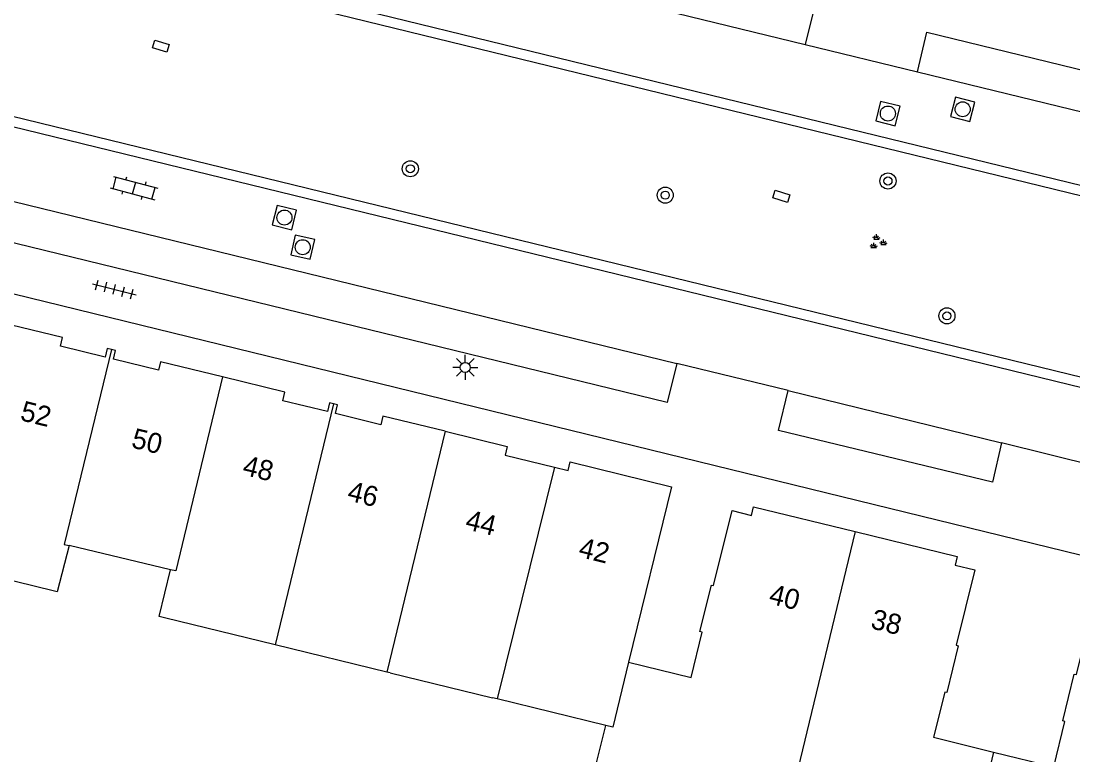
# Model space of a CAD drawing. Extents: x 125000 to 129004, y 397500 to 399008.
# Drawn here: x 126516.3 to 126568.7, y 397968.6 to 398005.2 of the extents above; entities that cross this region are included whole.
import ezdxf

# ---------------------------------------------------------------- set-up
doc = ezdxf.new("R2010")
doc.units = 0
for name, color, linetype in [('gg-anno-huisnummerreeks BGT', 7, 'Continuous'), ('gg-bbg-hoofdgebouw', 7, 'Continuous'), ('gg-bbg-tussenscheiding', 7, 'Continuous'), ('gg-knt-verharding', 7, 'Continuous'), ('gg-knt-verharding nz', 7, 'Continuous'), ('gt-symb-boom', 7, 'Continuous'), ('gt-symb-groenvak', 7, 'Continuous'), ('gt-symb-klinker verharding', 7, 'Continuous'), ('gt-symb-kolk center center', 7, 'Continuous'), ('gt-symb-lichtmast', 7, 'Continuous'), ('gt-symb-rioolschacht', 7, 'Continuous'), ('gt-symb-tegel verharding', 7, 'Continuous')]:
    doc.layers.add(name, color=color, linetype=linetype)

# ---------------------------------------------------------------- blocks, each defined once
blk = doc.blocks.new('gt0-BOOM')
at = {"layer": 'gt-symb-boom'}
for radius in [0.4, 0.2]:
    blk.add_circle((0, 0), radius, dxfattribs=at)
blk = doc.blocks.new('gt0-KOLKCC')
at = {"layer": 'gt-symb-kolk center center'}
blk.add_lwpolyline([(-0.375, 0.2), (0.375, 0.2), (0.375, -0.2), (-0.375, -0.2)], close=True, dxfattribs=at)
blk = doc.blocks.new('gt0-GRVAK')
at = {"layer": 'gt-symb-groenvak'}
for p, q in [((-0.11, 0.189), (-0.228, 0.24)), ((-0.182, 0.153), (0.088, 0.153)), ((-0.091, 0.211), (-0.156, 0.322)), ((-0.047, 0.214), (-0.047, 0.393)), ((-0.004, 0.211), (0.061, 0.322)), ((0.015, 0.189), (0.133, 0.24)), ((0.262, -0.052), (0.197, 0.059)), ((0.305, -0.049), (0.305, 0.13)), ((0.349, -0.052), (0.414, 0.059)), ((-0.245, -0.228), (-0.363, -0.177)), ((-0.318, -0.264), (-0.047, -0.264)), ((-0.226, -0.206), (-0.291, -0.095)), ((-0.183, -0.203), (-0.183, -0.024)), ((-0.139, -0.206), (-0.074, -0.095)), ((-0.12, -0.228), (-0.002, -0.177)), ((0.243, -0.074), (0.125, -0.023)), ((0.17, -0.11), (0.441, -0.11)), ((0.368, -0.074), (0.486, -0.023))]:
    blk.add_line(p, q, dxfattribs=at)
blk = doc.blocks.new('gt0-RS')
at = {"layer": 'gt-symb-rioolschacht'}
blk.add_lwpolyline([(-0.5, -0.5), (0.5, -0.5), (0.5, 0.5), (-0.5, 0.5)], close=True, dxfattribs=at)
blk.add_circle((0, 0), 0.375, dxfattribs=at)
blk = doc.blocks.new('gt0-LMAST')
at = {"layer": 'gt-symb-lichtmast'}
for p, q in [((-0.005, 0.246), (-0.005, 0.621)), ((-0.182, 0.173), (-0.447, 0.438)), ((0.172, 0.173), (0.437, 0.438)), ((-0.255, -0.004), (-0.63, -0.004)), ((-0.182, -0.181), (-0.447, -0.446)), ((-0.005, -0.254), (-0.005, -0.629)), ((0.437, -0.446), (0.172, -0.181)), ((0.245, -0.004), (0.62, -0.004))]:
    blk.add_line(p, q, dxfattribs=at)
blk.add_circle((-0.005, -0.004), 0.25, dxfattribs=at)
blk = doc.blocks.new('gt0-TEG1')
at = {"layer": 'gt-symb-tegel verharding'}
for p, q in [((-1.125, 0), (1.125, 0)), ((-0.9, -0.25), (-0.9, 0.25)), ((-0.45, -0.25), (-0.45, 0.25)), ((0, -0.25), (0, 0.25)), ((0.45, -0.25), (0.45, 0.25)), ((0.9, -0.25), (0.9, 0.25))]:
    blk.add_line(p, q, dxfattribs=at)
blk = doc.blocks.new('gt0-KL1')
at = {"layer": 'gt-symb-klinker verharding'}
for p, q in [((-1.15, 0.3), (1.15, 0.3)), ((-1, -0.3), (-1, 0.3)), ((-0.5, 0.3), (-0.5, 0.45)), ((0, -0.3), (0, 0.3)), ((0.5, 0.3), (0.5, 0.45)), ((1, -0.3), (1, 0.3)), ((-1.15, -0.3), (1.15, -0.3)), ((-0.5, -0.45), (-0.5, -0.3)), ((0.5, -0.45), (0.5, -0.3))]:
    blk.add_line(p, q, dxfattribs=at)

msp = doc.modelspace()

# ---------------------------------------------------------------- linework, layer by layer
at = {"layer": 'gg-bbg-hoofdgebouw'}
for p, q in [((126523.748, 397977.83), (126518.69, 397979.033)), ((126517.898, 397976.782), (126512.367, 397978.142)), ((126528.968, 397974.085), (126523.444, 397975.434)), ((126534.524, 397972.728), (126528.968, 397974.085)), ((126534.689, 397972.688), (126534.524, 397972.728)), ((126534.689, 397972.688), (126539.79, 397971.449)), ((126540.026, 397971.391), (126539.79, 397971.449)), ((126545.43, 397970.064), (126540.026, 397971.391)), ((126544.688, 397967.042), (126545.43, 397970.064))]:
    msp.add_line(p, q, dxfattribs=at)
for points in [[(126520.802, 397988.798), (126520.593, 397988.849), (126520.488, 397988.421), (126518.259, 397988.968), (126518.364, 397989.396), (126515.27, 397990.154)], [(126526.345, 397987.439), (126523.25, 397988.196), (126523.145, 397987.768), (126520.908, 397988.321), (126521.01, 397988.748), (126520.802, 397988.798)], [(126531.87, 397986.092), (126531.668, 397986.14), (126531.565, 397985.714), (126529.337, 397986.255), (126529.44, 397986.681), (126526.345, 397987.439)], [(126537.424, 397984.729), (126534.328, 397985.486), (126534.223, 397985.059), (126531.97, 397985.616), (126532.071, 397986.044), (126531.87, 397986.092)], [(126537.424, 397984.729), (126540.519, 397983.973), (126540.415, 397983.544), (126542.882, 397982.946)], [(126542.882, 397982.946), (126543.562, 397982.781), (126543.666, 397983.208), (126548.717, 397981.969), (126546.573, 397973.228)], [(126546.573, 397973.228), (126549.681, 397972.466), (126550.233, 397974.719), (126550.127, 397974.745), (126550.696, 397977.066), (126550.803, 397977.04), (126551.726, 397980.776), (126552.698, 397980.538), (126552.802, 397980.966), (126557.86, 397979.728)], [(126557.86, 397979.728), (126562.949, 397978.486), (126562.845, 397978.059), (126563.816, 397977.822), (126562.893, 397974.066), (126563, 397974.039), (126562.427, 397971.708), (126562.32, 397971.734), (126561.766, 397969.48), (126564.761, 397968.744)], [(126518.69, 397979.033), (126518.098, 397976.733), (126517.898, 397976.782)], [(126523.444, 397975.434), (126523.179, 397975.499), (126523.748, 397977.83)], [(126564.761, 397968.744), (126567.756, 397968.008), (126568.313, 397970.271), (126568.205, 397970.298), (126568.778, 397972.63), (126568.886, 397972.603), (126569.912, 397976.779), (126575.108, 397975.515), (126575.004, 397975.088), (126576.346, 397974.759), (126575.631, 397971.842), (126576.642, 397971.594), (126575.654, 397967.559), (126574.642, 397967.807), (126573.929, 397964.895)]]:
    msp.add_lwpolyline(points, dxfattribs=at)
at = {"layer": 'gg-bbg-tussenscheiding'}
for p, q in [((126531.87, 397986.092), (126528.968, 397974.085)), ((126537.424, 397984.729), (126534.524, 397972.728)), ((126542.882, 397982.946), (126540.026, 397971.391)), ((126557.86, 397979.728), (126554.796, 397967.048)), ((126564.761, 397968.744), (126563.253, 397962.507))]:
    msp.add_line(p, q, dxfattribs=at)
for points in [[(126520.802, 397988.798), (126518.455, 397979.089), (126518.69, 397979.033)], [(126526.345, 397987.439), (126524.008, 397977.768), (126523.748, 397977.83)], [(126546.573, 397973.228), (126545.787, 397969.976), (126545.43, 397970.064)]]:
    msp.add_lwpolyline(points, dxfattribs=at)
at = {"layer": 'gg-knt-verharding'}
for p, q in [((126680.269, 397969.791), (126484.428, 398017.669)), ((126682.484, 397968.735), (126484.508, 398017.135)), ((126417.28, 398015.702), (126579.422, 397976.046)), ((126482.394, 398008.606), (126680.419, 397960.251)), ((126482.075, 398008.169), (126677.934, 397960.343)), ((126555.377, 398004), (126560.966, 398002.653)), ((126554.519, 397986.758), (126548.971, 397988.104)), ((126571.6, 397982.555), (126565.152, 397984.146))]:
    msp.add_line(p, q, dxfattribs=at)
for points in [[(126500.727, 398017.394), (126501.227, 398019.359), (126555.856, 398005.956), (126555.377, 398004)], [(126560.966, 398002.653), (126561.436, 398004.622), (126572.126, 398002.008), (126571.643, 398000.033)], [(126548.971, 397988.104), (126548.501, 397986.164), (126506.157, 397996.492), (126506.651, 397998.453)], [(126565.152, 397984.146), (126564.705, 397982.193), (126554.035, 397984.772), (126554.519, 397986.758)]]:
    msp.add_lwpolyline(points, dxfattribs=at)
at = {"layer": 'gg-knt-verharding nz'}
for p, q in [((126500.727, 398017.394), (126555.377, 398004)), ((126560.966, 398002.653), (126571.643, 398000.033)), ((126506.651, 397998.453), (126548.971, 397988.104)), ((126554.519, 397986.758), (126565.152, 397984.146))]:
    msp.add_line(p, q, dxfattribs=at)

# ---------------------------------------------------------------- block references
at = {"layer": 'gt-symb-boom'}
for p in [(126535.696, 397997.814), (126559.495, 397997.204), (126548.397, 397996.498), (126562.433, 397990.483)]:
    msp.add_blockref('gt0-BOOM', p, dxfattribs=at)
at = {"layer": 'gt-symb-groenvak'}
msp.add_blockref('gt0-GRVAK', (126558.967, 397994.153), dxfattribs=at)
at = {"layer": 'gt-symb-klinker verharding', "rotation": -14.828108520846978}
msp.add_blockref('gt0-KL1', (126521.935, 397996.851), dxfattribs=at)
at = {"layer": 'gt-symb-kolk center center'}
for p, rotation in [((126523.27, 398003.924), 163.1416012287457), ((126554.182, 397996.44), 162.96046487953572)]:
    msp.add_blockref('gt0-KOLKCC', p, dxfattribs=dict(at, rotation=rotation))
at = {"layer": 'gt-symb-lichtmast'}
msp.add_blockref('gt0-LMAST', (126538.437, 397987.916), dxfattribs=at)
at = {"layer": 'gt-symb-rioolschacht'}
for p, rotation in [((126559.491, 398000.567), -14.008443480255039), ((126563.217, 398000.778), -14.591956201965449), ((126529.423, 397995.38), 166.28353067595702), ((126530.334, 397993.904), 167.3531465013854)]:
    msp.add_blockref('gt0-RS', p, dxfattribs=dict(at, rotation=rotation))
at = {"layer": 'gt-symb-tegel verharding', "rotation": -14.425531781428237}
msp.add_blockref('gt0-TEG1', (126520.952, 397991.803), dxfattribs=at)

# ---------------------------------------------------------------- texts
at = {"layer": 'gg-anno-huisnummerreeks BGT'}
for s, rotation, p in [('52', 346.2, (126516.21, 397985.29)), ('50', 346.2, (126521.747, 397983.933)), ('48', 346.3, (126527.287, 397982.577)), ('46', 346.2, (126532.507, 397981.299)), ('44', 346.3, (126538.386, 397979.863)), ('42', 346.2, (126544.026, 397978.485)), ('40', 346.2, (126553.509, 397976.16)), ('38', 346.3, (126558.584, 397974.919))]:
    msp.add_text(s, height=1, rotation=rotation, dxfattribs=at).set_placement(p)

doc.saveas('drawing.dxf')
